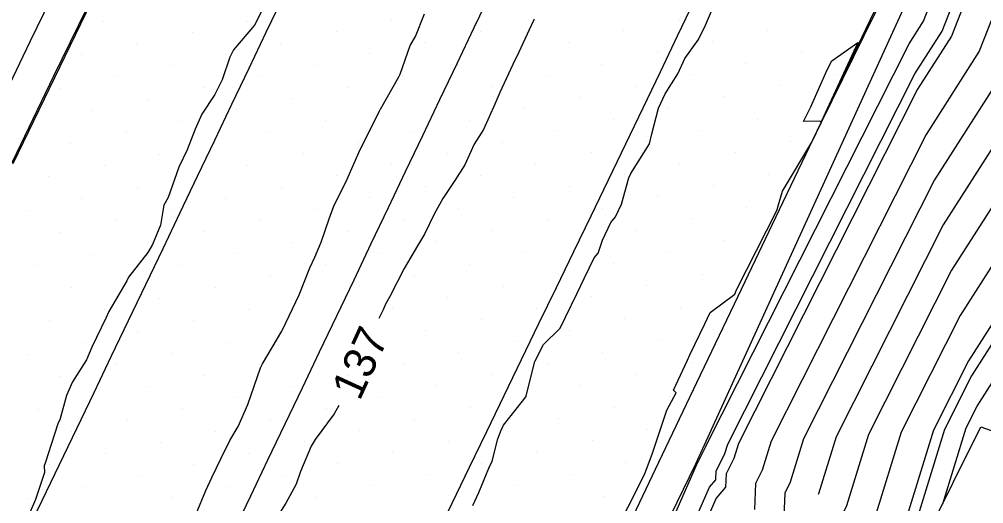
# Model space of a CAD drawing. Extents: x 2354170 to 2357230, y 866100 to 868290.
# Drawn here: x 2355406.9 to 2355467.3, y 866650.4 to 866680.7 of the extents above; entities that cross this region are included whole.
import ezdxf

# ---------------------------------------------------------------- set-up
doc = ezdxf.new("R2010")
doc.units = 0
for name, color, linetype in [('Default', 7, 'Continuous'), ('DTM Contours Major', 7, 'Continuous'), ('DTM Contours Minor', 7, 'Continuous'), ('DTM Contours Minor Text', 7, 'Continuous'), ('Exist DTM Breakline', 7, 'Continuous'), ('Exist DTM Scan Elevation Point', 7, 'Continuous'), ('Exist Roads EOP', 7, 'Continuous'), ('PH Exist DTM Breakline', 7, 'Continuous')]:
    doc.layers.add(name, color=color, linetype=linetype)

msp = doc.modelspace()

# ---------------------------------------------------------------- linework, layer by layer
at = {"layer": 'Default'}
for points in [[(2355437.783, 866626.452), (2355449.335, 866652.771), (2355449.355, 866652.795), (2355449.356, 866652.824), (2355449.926, 866653.941), (2355449.944, 866653.999), (2355462.662, 866679.159), (2355463.568, 866680.576), (2355469.6, 866695.977), (2355469.805, 866696.397), (2355471.533, 866699.231), (2355485.088, 866721.476), (2355486.408, 866724.199), (2355486.785, 866725.068), (2355488.656, 866729.002), (2355498.814, 866752.688), (2355499.054, 866753.342), (2355499.721, 866754.794), (2355510.04, 866777.059)], [(2355501.286, 866748.941), (2355493.582, 866730.98), (2355489.577, 866722.559), (2355489.296, 866721.908), (2355486.503, 866716.149), (2355476.289, 866699.388), (2355474.987, 866697.252), (2355471.651, 866690.432), (2355467.052, 866678.69), (2355463.725, 866673.487), (2355454.015, 866654.276), (2355453.455, 866652.457), (2355453.031, 866651.627), (2355452.969, 866650)], [(2355502.522, 866747.068), (2355496.046, 866731.969), (2355490.974, 866721.304), (2355490.74, 866720.763), (2355487.211, 866713.486), (2355478.667, 866699.466), (2355477.578, 866697.679), (2355472.677, 866687.66), (2355468.794, 866677.747), (2355464.257, 866670.651), (2355456.051, 866654.415), (2355455.219, 866651.715), (2355454.868, 866651.028), (2355454.776, 866648.602)], [(2355438.721, 866742.718), (2355436.29, 866737.818), (2355433.895, 866732.911), (2355431.454, 866728.12), (2355430.057, 866725.807), (2355427.613, 866720.941), (2355425.229, 866716.088), (2355422.879, 866711.237), (2355422.189, 866709.746), (2355419.87, 866704.878), (2355417.537, 866700.02), (2355415.241, 866695.136), (2355414.131, 866692.744), (2355411.957, 866688.23), (2355409.771, 866683.741), (2355407.587, 866679.28), (2355405.43, 866674.782)], [(2355501.607, 866740.18), (2355498.509, 866732.957), (2355492.37, 866720.049), (2355492.183, 866719.618), (2355487.918, 866710.822), (2355481.045, 866699.544), (2355480.169, 866698.107), (2355473.702, 866684.888), (2355470.536, 866676.804), (2355464.789, 866667.814), (2355458.086, 866654.554), (2355456.983, 866650.973), (2355456.965, 866650.938)], [(2355503.435, 866734.935), (2355495.163, 866717.54), (2355495.071, 866717.327), (2355489.333, 866705.496), (2355485.801, 866699.7), (2355485.351, 866698.961), (2355475.753, 866679.343), (2355474.02, 866674.918), (2355465.852, 866662.142), (2355462.157, 866654.832), (2355460.511, 866649.49), (2355460.38, 866649.232), (2355460.197, 866644.41), (2355456.778, 866640.382), (2355453.027, 866631.837), (2355450.389, 866626.974), (2355440.973, 866609.615), (2355439.49, 866606.291), (2355437.468, 866601.458), (2355433.274, 866592.65), (2355424.806, 866571.951)], [(2355500.972, 866733.946), (2355493.766, 866718.795), (2355493.627, 866718.472), (2355488.626, 866708.159), (2355483.423, 866699.622), (2355482.76, 866698.534), (2355474.728, 866682.115), (2355472.278, 866675.861), (2355465.321, 866664.978), (2355460.122, 866654.693), (2355458.747, 866650.232), (2355458.543, 866649.831), (2355458.39, 866645.807), (2355455.537, 866642.447), (2355450.486, 866630.939), (2355448.246, 866626.809), (2355440.247, 866612.063), (2355438.362, 866607.839), (2355436.636, 866603.712), (2355431.174, 866592.241), (2355423.936, 866574.547)], [(2355497.706, 866718.698), (2355496.559, 866716.285), (2355496.514, 866716.182), (2355490.041, 866702.832), (2355488.179, 866699.778), (2355487.942, 866699.389), (2355476.779, 866676.571), (2355475.762, 866673.975), (2355466.384, 866659.306), (2355464.193, 866654.971), (2355462.275, 866648.748), (2355462.217, 866648.634), (2355462.004, 866643.012), (2355458.018, 866638.317), (2355455.568, 866632.734), (2355453.962, 866629.774)], [(2355482.318, 866713.105), (2355473.911, 866699.31), (2355472.396, 866696.824), (2355470.625, 866693.205), (2355465.31, 866679.633), (2355463.194, 866676.323), (2355451.979, 866654.138), (2355451.69, 866653.199), (2355451.194, 866652.225), (2355451.162, 866651.397), (2355450.575, 866650.706), (2355440.324, 866627.349), (2355439.672, 866626.147), (2355438.31, 866623.637)], [(2355464.763, 866650.353), (2355466.229, 866655.11), (2355466.916, 866656.47), (2355477.504, 866673.032), (2355477.804, 866673.798), (2355490.533, 866699.816), (2355490.557, 866699.856), (2355490.748, 866700.169), (2355495.551, 866710.073), (2355491.189, 866700.061), (2355490.989, 866699.684), (2355490.982, 866699.671), (2355479.389, 866673.277), (2355478.989, 866672.39), (2355472.959, 866655.692), (2355471.375, 866653.411), (2355469.261, 866652.374), (2355467.119, 866646.636)], [(2355444.023, 866648.094), (2355446.065, 866652.154), (2355446.261, 866652.637), (2355446.581, 866653.526), (2355447.491, 866656.229), (2355448.068, 866657.298), (2355447.913, 866657.482), (2355448.771, 866659.353), (2355448.932, 866659.685), (2355449.861, 866661.629), (2355450.198, 866662.327), (2355451.752, 866663.48), (2355451.854, 866663.748), (2355454.355, 866668.669), (2355454.39, 866668.782), (2355454.461, 866669.018), (2355454.721, 866669.921), (2355456.563, 866673.009), (2355457.176, 866674.256), (2355459.851, 866679.687), (2355462.304, 866684.664), (2355464.561, 866689.243), (2355465.088, 866690.663), (2355467.597, 866695.859)], [(2355396.799, 866648.979), (2355397.446, 866650.438), (2355398.545, 866652.804), (2355399.178, 866654.281), (2355399.575, 866655.252), (2355400.603, 866657.818), (2355400.731, 866658.163), (2355400.854, 866658.386), (2355401.919, 866660.374), (2355401.997, 866660.575), (2355402.374, 866661.753), (2355403.771, 866665.381), (2355404.015, 866666.052), (2355404.117, 866666.297), (2355404.177, 866666.44), (2355404.816, 866668.091), (2355406.443, 866671.648), (2355406.509, 866671.771), (2355409.093, 866677.159), (2355411.709, 866682.502), (2355414.326, 866687.878), (2355416.931, 866693.285), (2355416.937, 866693.299)], [(2355422.101, 866681.188), (2355421.667, 866680.317), (2355420.358, 866678.771), (2355420.127, 866678.327), (2355419.633, 866676.906), (2355419.18, 866675.993), (2355418.366, 866674.747), (2355417.954, 866673.82), (2355417.453, 866672.519), (2355416.927, 866671.428), (2355416.255, 866669.544), (2355415.979, 866669.058), (2355415.776, 866667.81), (2355415.27, 866666.598), (2355414.994, 866666.088), (2355413.784, 866664.546), (2355413.667, 866664.322), (2355412.549, 866662.393), (2355412.353, 866661.972), (2355411.487, 866660.154), (2355411.144, 866659.362), (2355410.261, 866657.986), (2355409.894, 866657.131), (2355409.468, 866655.605), (2355409.382, 866655.437), (2355409.122, 866654.658), (2355408.583, 866652.967), (2355408.488, 866652.725), (2355408.521, 866652.312), (2355407.958, 866650.636), (2355407.351, 866649.237)], [(2355435.334, 866650.257), (2355435.722, 866651.055), (2355436.346, 866652.585), (2355436.551, 866653.028), (2355436.897, 866654.425), (2355437.113, 866654.962), (2355437.265, 866655.272), (2355438.453, 866656.777), (2355438.666, 866657.045), (2355438.676, 866657.069), (2355438.676, 866657.114), (2355439.212, 866659.258), (2355439.755, 866660.323), (2355440.807, 866661.352), (2355441.137, 866662.05), (2355441.874, 866663.543), (2355442.312, 866664.469), (2355442.927, 866665.755), (2355443.192, 866666.042), (2355443.454, 866666.868), (2355443.98, 866667.979), (2355444.265, 866668.329), (2355444.641, 866669.108), (2355445.113, 866670.766), (2355445.233, 866671.032), (2355446.412, 866672.904), (2355446.539, 866673.53), (2355446.958, 866675.125), (2355447.381, 866676.024), (2355448.176, 866677.281), (2355448.622, 866678.233), (2355449.478, 866679.43), (2355449.9, 866680.332), (2355450.468, 866681.638)], [(2355457.152, 866674.28), (2355457.059, 866674.31), (2355456.042, 866674.3), (2355456.503, 866675.221), (2355456.566, 866675.348), (2355457.535, 866677.535), (2355457.812, 866678.089), (2355459.455, 866679.242), (2355457.152, 866674.28)]]:
    msp.add_lwpolyline(points, dxfattribs=at)
at = {"layer": 'DTM Contours Major'}
msp.add_lwpolyline([(2355501.607, 866740.18), (2355498.509, 866732.957), (2355492.37, 866720.049), (2355492.183, 866719.618), (2355487.918, 866710.822), (2355481.045, 866699.544), (2355480.169, 866698.107), (2355473.702, 866684.888), (2355470.536, 866676.804), (2355464.789, 866667.814), (2355458.086, 866654.554), (2355456.983, 866650.973), (2355456.965, 866650.938)], dxfattribs=at)
at = {"layer": 'DTM Contours Minor'}
for points in [[(2355428.649, 866604.28), (2355433.029, 866613.479), (2355433.476, 866614.546), (2355437.102, 866622.672), (2355438.957, 866626.092), (2355439.477, 866627.05), (2355450.162, 866651.394), (2355450.56, 866651.863), (2355450.581, 866652.425), (2355451.102, 866653.447), (2355451.301, 866654.091), (2355463.016, 866677.268), (2355464.73, 866679.948), (2355470.284, 866694.129), (2355471.533, 866696.682), (2355473.118, 866699.283), (2355485.56, 866719.7), (2355487.371, 866723.435), (2355487.716, 866724.232), (2355490.298, 866729.662), (2355499.638, 866751.439), (2355500.106, 866752.715)], [(2355488.549, 866699.006), (2355477.121, 866675.646), (2355476.343, 866673.661), (2355466.561, 866658.361), (2355464.871, 866655.018), (2355462.863, 866648.5), (2355462.83, 866648.434), (2355462.606, 866642.546), (2355458.432, 866637.629), (2355456.415, 866633.033), (2355453.247, 866627.195), (2355441.941, 866606.351), (2355440.993, 866604.227), (2355438.577, 866598.452), (2355436.075, 866593.197), (2355425.967, 866568.489)], [(2355418.004, 866649.732), (2355418.618, 866651.18), (2355419.023, 866652.055), (2355419.549, 866653.173), (2355420.126, 866654.324), (2355420.652, 866655.202), (2355421.251, 866656.577), (2355422.038, 866658.866), (2355422.114, 866659.004), (2355422.169, 866659.119), (2355423.384, 866661.161), (2355423.386, 866661.161), (2355423.419, 866661.239), (2355424.467, 866663.442), (2355425.126, 866665.134), (2355425.447, 866665.791), (2355425.847, 866666.738), (2355426.352, 866668.19), (2355426.656, 866669.053), (2355427.386, 866670.504), (2355428.274, 866672.538), (2355428.423, 866672.815), (2355429.501, 866674.962), (2355429.544, 866675.054), (2355429.551, 866675.067), (2355430.711, 866677.095), (2355430.787, 866677.247), (2355431.407, 866679.041), (2355431.74, 866679.614), (2355432.304, 866681.028)], [(2355439.17, 866680.693), (2355439.132, 866680.614), (2355438.856, 866680.04), (2355438.226, 866678.626), (2355438.105, 866678.4), (2355437.96, 866678.125), (2355437.037, 866676.109), (2355436.717, 866675.372), (2355436.009, 866673.791), (2355435.42, 866672.878), (2355434.828, 866671.576), (2355434.213, 866670.592), (2355433.468, 866669.478), (2355432.932, 866668.527), (2355432.312, 866667.245), (2355431.864, 866666.506), (2355431.049, 866665.083), (2355430.149, 866663.329), (2355429.871, 866662.865), (2355429.716, 866662.504), (2355429.446, 866661.955)], [(2355426.954, 866656.517), (2355426.664, 866655.993), (2355425.473, 866654.38), (2355425.212, 866653.957), (2355424.554, 866652.389), (2355424.269, 866651.583), (2355423.636, 866650.398), (2355423.011, 866649.417)]]:
    msp.add_lwpolyline(points, dxfattribs=at)
at = {"layer": 'Exist DTM Breakline'}
for points in [[(2355420.348, 866648.601), (2355421.428, 866650.856), (2355422.508, 866653.111), (2355423.587, 866655.365), (2355424.667, 866657.62), (2355425.747, 866659.875), (2355426.822, 866662.132), (2355427.898, 866664.389), (2355428.973, 866666.646), (2355430.048, 866668.903), (2355431.124, 866671.159), (2355432.2, 866673.416), (2355433.276, 866675.672), (2355434.353, 866677.929), (2355435.429, 866680.185), (2355436.505, 866682.442)], [(2355407.282, 866648.321), (2355408.365, 866650.574), (2355409.449, 866652.828), (2355410.532, 866655.08), (2355411.616, 866657.333), (2355412.7, 866659.586), (2355413.784, 866661.839), (2355414.862, 866664.094), (2355415.941, 866666.35), (2355417.019, 866668.605), (2355418.097, 866670.861), (2355419.173, 866673.118), (2355420.249, 866675.374), (2355421.324, 866677.631), (2355422.4, 866679.888), (2355423.472, 866682.146)], [(2355449.222, 866681.896), (2355448.142, 866679.642), (2355447.063, 866677.386), (2355445.985, 866675.131), (2355444.906, 866672.875), (2355443.821, 866670.623), (2355442.731, 866668.374), (2355441.64, 866666.124), (2355440.55, 866663.874), (2355439.461, 866661.624), (2355438.372, 866659.374), (2355437.283, 866657.123), (2355436.194, 866654.873), (2355435.106, 866652.622), (2355434.018, 866650.371), (2355432.93, 866648.12)]]:
    msp.add_lwpolyline(points, dxfattribs=at)
at = {"layer": 'Exist DTM Scan Elevation Point'}
for p, q in [((2355412.211, 866680.544), (2355412.211, 866680.544)), ((2355421.224, 866680.575), (2355421.224, 866680.575)), ((2355430.238, 866680.607), (2355430.238, 866680.607)), ((2355439.252, 866680.639), (2355439.252, 866680.639)), ((2355448.266, 866680.67), (2355448.266, 866680.67)), ((2355426.774, 866679.902), (2355426.774, 866679.902)), ((2355435.788, 866679.933), (2355435.788, 866679.933)), ((2355444.802, 866679.965), (2355444.802, 866679.965)), ((2355453.815, 866679.997), (2355453.815, 866679.997)), ((2355417.76, 866679.87), (2355417.76, 866679.87)), ((2355414.296, 866679.164), (2355414.296, 866679.164)), ((2355423.309, 866679.196), (2355423.309, 866679.196)), ((2355432.323, 866679.228), (2355432.323, 866679.228)), ((2355441.337, 866679.259), (2355441.337, 866679.259)), ((2355450.351, 866679.291), (2355450.351, 866679.291)), ((2355410.831, 866678.459), (2355410.831, 866678.459)), ((2355419.845, 866678.49), (2355419.845, 866678.49)), ((2355428.859, 866678.522), (2355428.859, 866678.522)), ((2355437.873, 866678.554), (2355437.873, 866678.554)), ((2355446.887, 866678.585), (2355446.887, 866678.585)), ((2355455.9, 866678.617), (2355455.9, 866678.617)), ((2355416.381, 866677.785), (2355416.381, 866677.785)), ((2355425.394, 866677.817), (2355425.394, 866677.817)), ((2355434.408, 866677.848), (2355434.408, 866677.848)), ((2355443.422, 866677.88), (2355443.422, 866677.88)), ((2355452.436, 866677.912), (2355452.436, 866677.912)), ((2355412.916, 866677.079), (2355412.916, 866677.079)), ((2355421.93, 866677.111), (2355421.93, 866677.111)), ((2355430.944, 866677.143), (2355430.944, 866677.143)), ((2355439.958, 866677.174), (2355439.958, 866677.174)), ((2355448.972, 866677.206), (2355448.972, 866677.206)), ((2355457.985, 866677.238), (2355457.985, 866677.238)), ((2355409.452, 866676.374), (2355409.452, 866676.374)), ((2355418.466, 866676.405), (2355418.466, 866676.405)), ((2355427.479, 866676.437), (2355427.479, 866676.437)), ((2355436.493, 866676.469), (2355436.493, 866676.469)), ((2355445.507, 866676.5), (2355445.507, 866676.5)), ((2355454.521, 866676.532), (2355454.521, 866676.532)), ((2355415.001, 866675.7), (2355415.001, 866675.7)), ((2355424.015, 866675.732), (2355424.015, 866675.732)), ((2355433.029, 866675.763), (2355433.029, 866675.763)), ((2355442.043, 866675.795), (2355442.043, 866675.795)), ((2355451.056, 866675.827), (2355451.056, 866675.827)), ((2355438.578, 866675.089), (2355438.578, 866675.089)), ((2355447.592, 866675.121), (2355447.592, 866675.121)), ((2355456.606, 866675.153), (2355456.606, 866675.153)), ((2355411.537, 866674.994), (2355411.537, 866674.994)), ((2355420.551, 866675.026), (2355420.551, 866675.026)), ((2355429.564, 866675.058), (2355429.564, 866675.058)), ((2355417.086, 866674.32), (2355417.086, 866674.32)), ((2355426.1, 866674.352), (2355426.1, 866674.352)), ((2355435.114, 866674.384), (2355435.114, 866674.384)), ((2355444.128, 866674.415), (2355444.128, 866674.415)), ((2355453.141, 866674.447), (2355453.141, 866674.447)), ((2355413.622, 866673.615), (2355413.622, 866673.615)), ((2355422.636, 866673.647), (2355422.636, 866673.647)), ((2355431.649, 866673.678), (2355431.649, 866673.678)), ((2355440.663, 866673.71), (2355440.663, 866673.71)), ((2355449.677, 866673.742), (2355449.677, 866673.742)), ((2355410.157, 866672.909), (2355410.157, 866672.909)), ((2355419.171, 866672.941), (2355419.171, 866672.941)), ((2355428.185, 866672.973), (2355428.185, 866672.973)), ((2355437.199, 866673.004), (2355437.199, 866673.004)), ((2355446.213, 866673.036), (2355446.213, 866673.036)), ((2355455.226, 866673.068), (2355455.226, 866673.068)), ((2355415.707, 866672.235), (2355415.707, 866672.235)), ((2355424.721, 866672.267), (2355424.721, 866672.267)), ((2355433.734, 866672.299), (2355433.734, 866672.299)), ((2355442.748, 866672.331), (2355442.748, 866672.331)), ((2355451.762, 866672.362), (2355451.762, 866672.362)), ((2355412.242, 866671.53), (2355412.242, 866671.53)), ((2355421.256, 866671.562), (2355421.256, 866671.562)), ((2355430.27, 866671.593), (2355430.27, 866671.593)), ((2355439.284, 866671.625), (2355439.284, 866671.625)), ((2355448.298, 866671.657), (2355448.298, 866671.657)), ((2355417.792, 866670.856), (2355417.792, 866670.856)), ((2355426.806, 866670.888), (2355426.806, 866670.888)), ((2355435.819, 866670.919), (2355435.819, 866670.919)), ((2355444.833, 866670.951), (2355444.833, 866670.951)), ((2355453.847, 866670.983), (2355453.847, 866670.983)), ((2355408.778, 866670.824), (2355408.778, 866670.824)), ((2355441.369, 866670.246), (2355441.369, 866670.246)), ((2355450.383, 866670.277), (2355450.383, 866670.277)), ((2355414.327, 866670.15), (2355414.327, 866670.15)), ((2355423.341, 866670.182), (2355423.341, 866670.182)), ((2355432.355, 866670.214), (2355432.355, 866670.214)), ((2355410.863, 866669.445), (2355410.863, 866669.445)), ((2355419.877, 866669.477), (2355419.877, 866669.477)), ((2355428.891, 866669.508), (2355428.891, 866669.508)), ((2355437.904, 866669.54), (2355437.904, 866669.54)), ((2355446.918, 866669.572), (2355446.918, 866669.572)), ((2355407.398, 866668.739), (2355407.398, 866668.739)), ((2355416.412, 866668.771), (2355416.412, 866668.771)), ((2355425.426, 866668.803), (2355425.426, 866668.803)), ((2355434.44, 866668.834), (2355434.44, 866668.834)), ((2355443.454, 866668.866), (2355443.454, 866668.866)), ((2355452.468, 866668.898), (2355452.468, 866668.898)), ((2355412.948, 866668.065), (2355412.948, 866668.065)), ((2355421.962, 866668.097), (2355421.962, 866668.097)), ((2355430.976, 866668.129), (2355430.976, 866668.129)), ((2355439.989, 866668.161), (2355439.989, 866668.161)), ((2355449.003, 866668.192), (2355449.003, 866668.192)), ((2355409.483, 866667.36), (2355409.483, 866667.36)), ((2355418.497, 866667.392), (2355418.497, 866667.392)), ((2355427.511, 866667.423), (2355427.511, 866667.423)), ((2355436.525, 866667.455), (2355436.525, 866667.455)), ((2355445.539, 866667.487), (2355445.539, 866667.487)), ((2355415.033, 866666.686), (2355415.033, 866666.686)), ((2355424.047, 866666.718), (2355424.047, 866666.718)), ((2355433.061, 866666.749), (2355433.061, 866666.749)), ((2355442.074, 866666.781), (2355442.074, 866666.781)), ((2355451.088, 866666.813), (2355451.088, 866666.813)), ((2355420.582, 866666.012), (2355420.582, 866666.012)), ((2355429.596, 866666.044), (2355429.596, 866666.044)), ((2355438.61, 866666.076), (2355438.61, 866666.076)), ((2355447.624, 866666.107), (2355447.624, 866666.107)), ((2355411.568, 866665.981), (2355411.568, 866665.981)), ((2355408.104, 866665.275), (2355408.104, 866665.275)), ((2355417.118, 866665.307), (2355417.118, 866665.307)), ((2355426.132, 866665.338), (2355426.132, 866665.338)), ((2355435.146, 866665.37), (2355435.146, 866665.37)), ((2355444.159, 866665.402), (2355444.159, 866665.402)), ((2355413.653, 866664.601), (2355413.653, 866664.601)), ((2355422.667, 866664.633), (2355422.667, 866664.633)), ((2355431.681, 866664.664), (2355431.681, 866664.664)), ((2355440.695, 866664.696), (2355440.695, 866664.696)), ((2355449.709, 866664.728), (2355449.709, 866664.728)), ((2355410.189, 866663.896), (2355410.189, 866663.896)), ((2355419.203, 866663.927), (2355419.203, 866663.927)), ((2355428.217, 866663.959), (2355428.217, 866663.959)), ((2355437.231, 866663.991), (2355437.231, 866663.991)), ((2355446.244, 866664.022), (2355446.244, 866664.022)), ((2355415.738, 866663.222), (2355415.738, 866663.222)), ((2355424.752, 866663.253), (2355424.752, 866663.253)), ((2355433.766, 866663.285), (2355433.766, 866663.285)), ((2355442.78, 866663.317), (2355442.78, 866663.317)), ((2355412.274, 866662.516), (2355412.274, 866662.516)), ((2355421.288, 866662.548), (2355421.288, 866662.548)), ((2355430.302, 866662.579), (2355430.302, 866662.579)), ((2355439.315, 866662.611), (2355439.315, 866662.611)), ((2355448.329, 866662.643), (2355448.329, 866662.643)), ((2355408.81, 866661.811), (2355408.81, 866661.811)), ((2355417.823, 866661.842), (2355417.823, 866661.842)), ((2355426.837, 866661.874), (2355426.837, 866661.874)), ((2355435.851, 866661.906), (2355435.851, 866661.906)), ((2355444.865, 866661.937), (2355444.865, 866661.937)), ((2355432.387, 866661.2), (2355432.387, 866661.2)), ((2355441.4, 866661.232), (2355441.4, 866661.232)), ((2355450.414, 866661.263), (2355450.414, 866661.263)), ((2355414.359, 866661.137), (2355414.359, 866661.137)), ((2355423.373, 866661.168), (2355423.373, 866661.168)), ((2355410.895, 866660.431), (2355410.895, 866660.431)), ((2355419.908, 866660.463), (2355419.908, 866660.463)), ((2355428.922, 866660.494), (2355428.922, 866660.494)), ((2355437.936, 866660.526), (2355437.936, 866660.526)), ((2355446.95, 866660.558), (2355446.95, 866660.558)), ((2355407.43, 866659.726), (2355407.43, 866659.726)), ((2355416.444, 866659.757), (2355416.444, 866659.757)), ((2355425.458, 866659.789), (2355425.458, 866659.789)), ((2355434.472, 866659.821), (2355434.472, 866659.821)), ((2355443.485, 866659.852), (2355443.485, 866659.852)), ((2355412.98, 866659.052), (2355412.98, 866659.052)), ((2355421.993, 866659.083), (2355421.993, 866659.083)), ((2355431.007, 866659.115), (2355431.007, 866659.115)), ((2355440.021, 866659.147), (2355440.021, 866659.147)), ((2355449.035, 866659.178), (2355449.035, 866659.178)), ((2355409.515, 866658.346), (2355409.515, 866658.346)), ((2355418.529, 866658.378), (2355418.529, 866658.378)), ((2355427.543, 866658.409), (2355427.543, 866658.409)), ((2355436.557, 866658.441), (2355436.557, 866658.441)), ((2355445.57, 866658.473), (2355445.57, 866658.473)), ((2355415.065, 866657.672), (2355415.065, 866657.672)), ((2355424.078, 866657.704), (2355424.078, 866657.704)), ((2355433.092, 866657.736), (2355433.092, 866657.736)), ((2355442.106, 866657.767), (2355442.106, 866657.767)), ((2355411.6, 866656.967), (2355411.6, 866656.967)), ((2355420.614, 866656.998), (2355420.614, 866656.998)), ((2355429.628, 866657.03), (2355429.628, 866657.03)), ((2355438.642, 866657.062), (2355438.642, 866657.062)), ((2355447.655, 866657.093), (2355447.655, 866657.093)), ((2355435.177, 866656.356), (2355435.177, 866656.356)), ((2355444.191, 866656.388), (2355444.191, 866656.388)), ((2355408.136, 866656.261), (2355408.136, 866656.261)), ((2355417.15, 866656.293), (2355417.15, 866656.293)), ((2355426.163, 866656.324), (2355426.163, 866656.324)), ((2355413.685, 866655.587), (2355413.685, 866655.587)), ((2355422.699, 866655.619), (2355422.699, 866655.619)), ((2355431.713, 866655.651), (2355431.713, 866655.651)), ((2355440.727, 866655.682), (2355440.727, 866655.682)), ((2355410.221, 866654.882), (2355410.221, 866654.882)), ((2355419.235, 866654.913), (2355419.235, 866654.913)), ((2355428.248, 866654.945), (2355428.248, 866654.945)), ((2355437.262, 866654.977), (2355437.262, 866654.977)), ((2355446.276, 866655.008), (2355446.276, 866655.008)), ((2355415.77, 866654.208), (2355415.77, 866654.208)), ((2355424.784, 866654.24), (2355424.784, 866654.24)), ((2355433.798, 866654.271), (2355433.798, 866654.271)), ((2355442.812, 866654.303), (2355442.812, 866654.303)), ((2355412.306, 866653.502), (2355412.306, 866653.502)), ((2355421.32, 866653.534), (2355421.32, 866653.534)), ((2355430.333, 866653.566), (2355430.333, 866653.566)), ((2355439.347, 866653.597), (2355439.347, 866653.597)), ((2355408.841, 866652.797), (2355408.841, 866652.797)), ((2355417.855, 866652.828), (2355417.855, 866652.828)), ((2355426.869, 866652.86), (2355426.869, 866652.86)), ((2355435.883, 866652.892), (2355435.883, 866652.892)), ((2355444.897, 866652.923), (2355444.897, 866652.923)), ((2355414.391, 866652.123), (2355414.391, 866652.123)), ((2355423.405, 866652.155), (2355423.405, 866652.155)), ((2355432.418, 866652.186), (2355432.418, 866652.186)), ((2355441.432, 866652.218), (2355441.432, 866652.218)), ((2355410.926, 866651.417), (2355410.926, 866651.417)), ((2355419.94, 866651.449), (2355419.94, 866651.449)), ((2355428.954, 866651.481), (2355428.954, 866651.481)), ((2355437.968, 866651.512), (2355437.968, 866651.512)), ((2355407.462, 866650.712), (2355407.462, 866650.712)), ((2355416.476, 866650.743), (2355416.476, 866650.743)), ((2355425.489, 866650.775), (2355425.489, 866650.775)), ((2355434.503, 866650.807), (2355434.503, 866650.807)), ((2355443.517, 866650.838), (2355443.517, 866650.838))]:
    msp.add_line(p, q, dxfattribs=at)
at = {"layer": 'Exist Roads EOP'}
for points in [[(2355406.549, 866671.658), (2355409.164, 866677.058), (2355411.77, 866682.463), (2355414.365, 866687.873), (2355416.947, 866693.288), (2355419.524, 866698.707), (2355422.1, 866704.126), (2355424.682, 866709.542), (2355427.274, 866714.953), (2355429.879, 866720.358), (2355432.494, 866725.758), (2355435.113, 866731.156), (2355437.73, 866736.555), (2355440.34, 866741.958), (2355442.939, 866747.366), (2355445.523, 866752.781), (2355448.099, 866758.2), (2355450.669, 866763.622), (2355453.238, 866769.044), (2355455.81, 866774.465), (2355458.388, 866779.883), (2355460.977, 866785.295), (2355463.574, 866790.704), (2355466.177, 866796.11)], [(2355444.205, 866647.111), (2355446.787, 866652.527), (2355449.368, 866657.943), (2355451.951, 866663.359), (2355454.537, 866668.773), (2355457.125, 866674.186), (2355459.716, 866679.598), (2355462.308, 866685.009), (2355464.901, 866690.42), (2355467.492, 866695.832), (2355470.082, 866701.244), (2355472.669, 866706.657), (2355475.256, 866712.071), (2355477.844, 866717.485), (2355480.432, 866722.897), (2355483.023, 866728.309), (2355485.616, 866733.72), (2355488.214, 866739.128), (2355490.814, 866744.536), (2355493.416, 866749.942), (2355496.02, 866755.348), (2355498.623, 866760.754), (2355501.225, 866766.16)]]:
    msp.add_lwpolyline(points, dxfattribs=at)
at = {"layer": 'PH Exist DTM Breakline'}
for points in [[(2355462.264, 866681.282), (2355449.29, 866652.845), (2355431.772, 866616.884), (2355416.85, 866585.734), (2355398.908, 866547.275), (2355381.513, 866510.255), (2355362.049, 866469.228), (2355342.769, 866429.753), (2355321.636, 866386.842), (2355298.704, 866337.728), (2355276.341, 866292.909), (2355263.024, 866269.789)], [(2355426.326, 866567.421), (2355443.653, 866600.576), (2355460.356, 866634.426), (2355464.036, 866641.441), (2355463.673, 866648.16), (2355467.159, 866655.174), (2355469.374, 866654.373), (2355472.135, 866653.045), (2355468.907, 866646.097), (2355466.55, 866646.807)]]:
    msp.add_lwpolyline(points, dxfattribs=at)

# ---------------------------------------------------------------- texts
at = {"layer": 'DTM Contours Minor Text'}
msp.add_text('137', height=2, rotation=65.37731, dxfattribs=at).set_placement((2355428.247, 866656.745))

doc.saveas('drawing.dxf')
